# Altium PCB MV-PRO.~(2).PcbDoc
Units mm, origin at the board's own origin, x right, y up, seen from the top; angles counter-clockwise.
Board outline 152.4 x 101.6 mm, 2 copper layers (Top Layer, Bottom Layer); 9 components, 6 nets, 20 pads, 0 vias.
Unrouted connection lines stored in the file: 14.
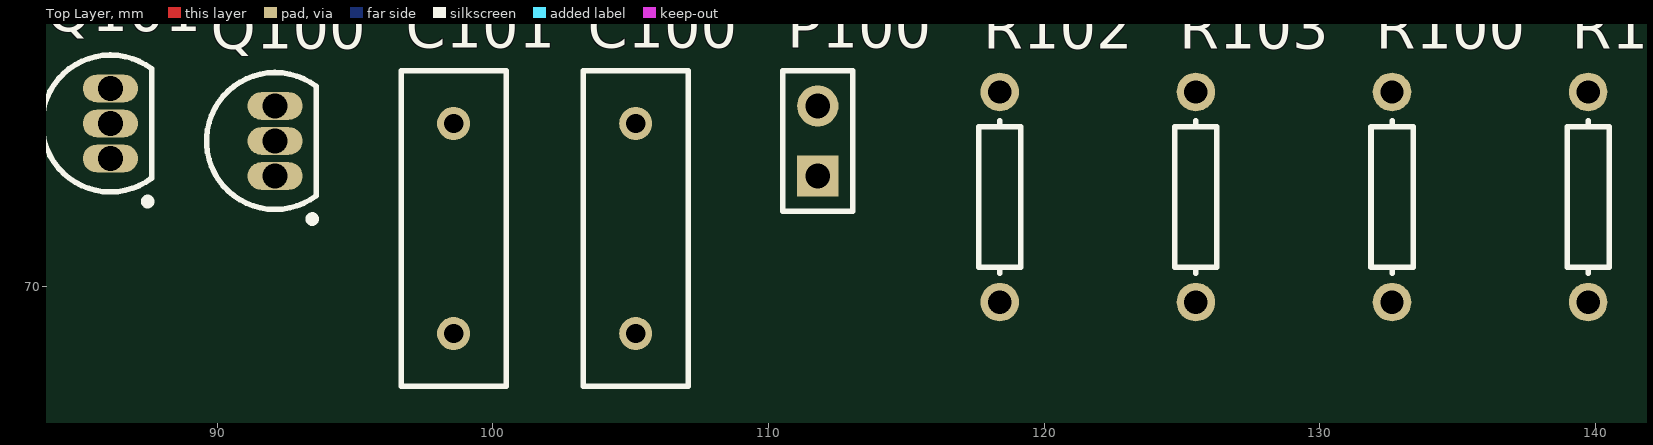
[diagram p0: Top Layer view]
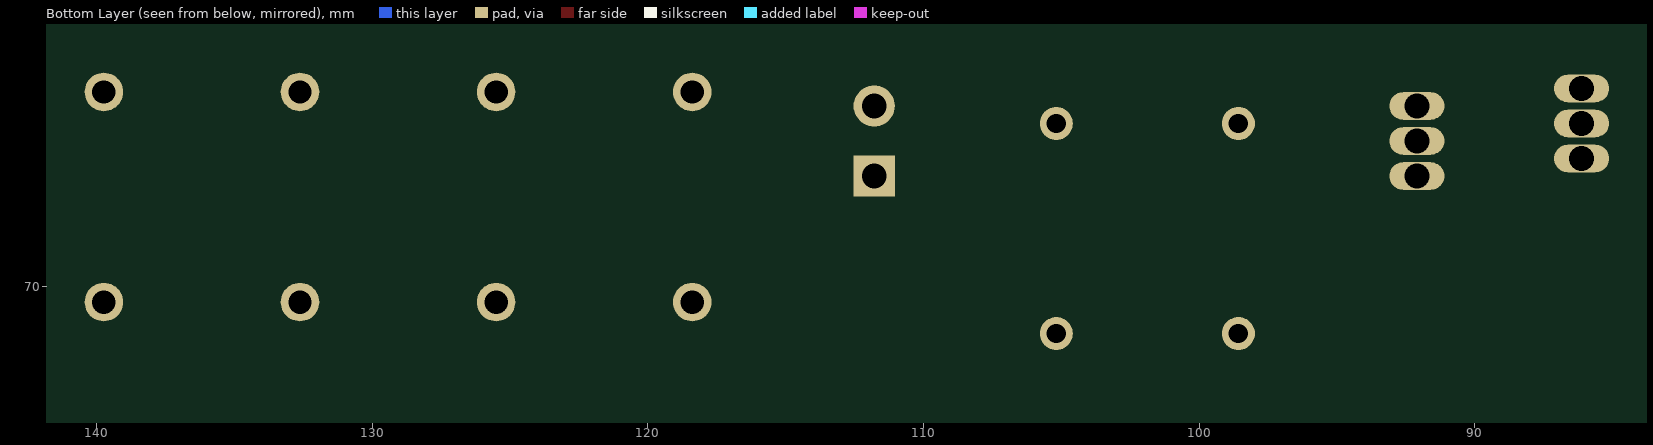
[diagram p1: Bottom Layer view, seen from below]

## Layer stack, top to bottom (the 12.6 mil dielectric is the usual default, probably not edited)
Top Solder: solder mask 0.0102, Solder Resist, Dk 3.5
Top Layer: signal copper 0.0356
Dielectric 1: dielectric 0.32, FR-4, Dk 4.8
Bottom Layer: signal copper 0.0356
Bottom Solder: solder mask 0.0102, Solder Resist, Dk 3.5

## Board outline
25.4,25.4 177.8,25.4 177.8,127 25.4,127

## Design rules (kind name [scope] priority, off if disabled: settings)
Clearance [All] p1: gap=0.254 ignorepadtopadclearanceinfootprint=FALSE except(0: Arc-Hole Track-Hole SMDPad-Hole THPad-Hole Via-Hole Fill-Hole Poly-Hole Region-Hole Text-Hole)
PolygonConnect [All] p1: connectstyle=Relief reliefconductorwidth=0.254 reliefentries=4 polygonreliefangle="90 Angle" airgapwidth=0.254
RoomDefinition test [InComponentClass('test')] p1: confinementstyle=ConfineIn formatcopy=TRUE lockcomponents=FALSE outline 82.702,66.116 144.424,66.116 144.424,80.594 82.702,80.594
RoutingVias [All] p1: holewidth=0.711 width=1.27 viastyle="Through Hole" minholewidth=0.711 minwidth=1.27 maxholewidth=0.711 maxwidth=1.27
SolderMaskExpansion [All] p1: expansion=0.102 istentingtop=FALSE
Width [All] p1: maxlimit=0.254 minlimit=0.254 preferedwidth=0.254
30 further rules are at their usual default settings.

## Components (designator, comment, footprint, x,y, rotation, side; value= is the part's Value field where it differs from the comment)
C100 "Cap" RAD-0.3 105.181,72.085 r90 top value=100pF
C101 "Cap" RAD-0.3 98.577,72.085 r90 top value=100pF
P100 "Header 2" HDR1X2 111.785,73.99 r90 top
Q100 "2N3904" TO-92A 92.1,75.26 r0 top
Q101 "2N3904" TO-92A 86.131,75.895 r0 top
R100 "Res1" AXIAL-0.3 132.613,73.228 r90 top value=1K
R101 "Res1" AXIAL-0.3 139.725,73.228 r90 top value=1K
R102 "Res1" AXIAL-0.3 118.389,73.228 r90 top value=1K
R103 "Res1" AXIAL-0.3 125.501,73.228 r90 top value=1K

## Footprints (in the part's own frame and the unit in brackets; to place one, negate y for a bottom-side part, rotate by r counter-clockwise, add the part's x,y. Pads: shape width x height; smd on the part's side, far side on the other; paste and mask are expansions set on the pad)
AXIAL-0.3 [mm] "Axial Device, Thru-Hole; 2 Leads; 0.3 in Pin Spacing"
  round 1.4 hole 0.85: 1(-3.81,0) 2(3.81,0)
  silkscreen extent -2.77,-0.76 2.77,0.76
HDR1X2 [mm] "Connector; Header; 2 Position"
  rect 1.5x1.5 hole 0.9: 1(0,0)
  round 1.5 hole 0.9: 2(2.54,0)
  silkscreen extent -1.27,-1.27 3.81,1.27
RAD-0.3 [mm] "Radial Cap, Thru-Hole; 2 Leads; 0.3 in Pin Spacing"
  round 1.2 hole 0.7: 1(-3.81,0) 2(3.81,0)
  silkscreen extent -5.71,-1.91 5.71,1.91
TO-92A [mm] "TO, Flat Index; 3 In-Line, Axial Leads; Body Dia. 4.5mm; Leads 0.51 x 0.48 mm (max)"
  oval 2x1 hole 0.9: 1(0,-1.27) 2(0,0) 3(0,1.27)
  silkscreen extent -2.48,-2.95 1.5,2.48, body extent -2.48,-2.5 1.5,2.5, height 6.86

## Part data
C100 C101: "Capacitor"
P100: "Header, 2-Pin"
Q100 Q101: "NPN General Purpose Amplifier"
R100 R101 R102 R103: "Resistor"

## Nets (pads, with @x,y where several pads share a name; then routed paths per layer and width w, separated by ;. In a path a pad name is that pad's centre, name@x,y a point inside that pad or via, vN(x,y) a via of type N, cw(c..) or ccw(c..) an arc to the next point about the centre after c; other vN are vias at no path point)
NetC100_1: C100.1 Q101.3 R101.2
NetC100_2: C100.2 Q100.2 R103.2
NetC101_1: C101.1 Q101.2 R100.2
NetC101_2: C101.2 Q100.3 R102.2
NetP100_1: P100.1 R100.1 R101.1 R102.1 R103.1
NetP100_2: P100.2 Q100.1 Q101.1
